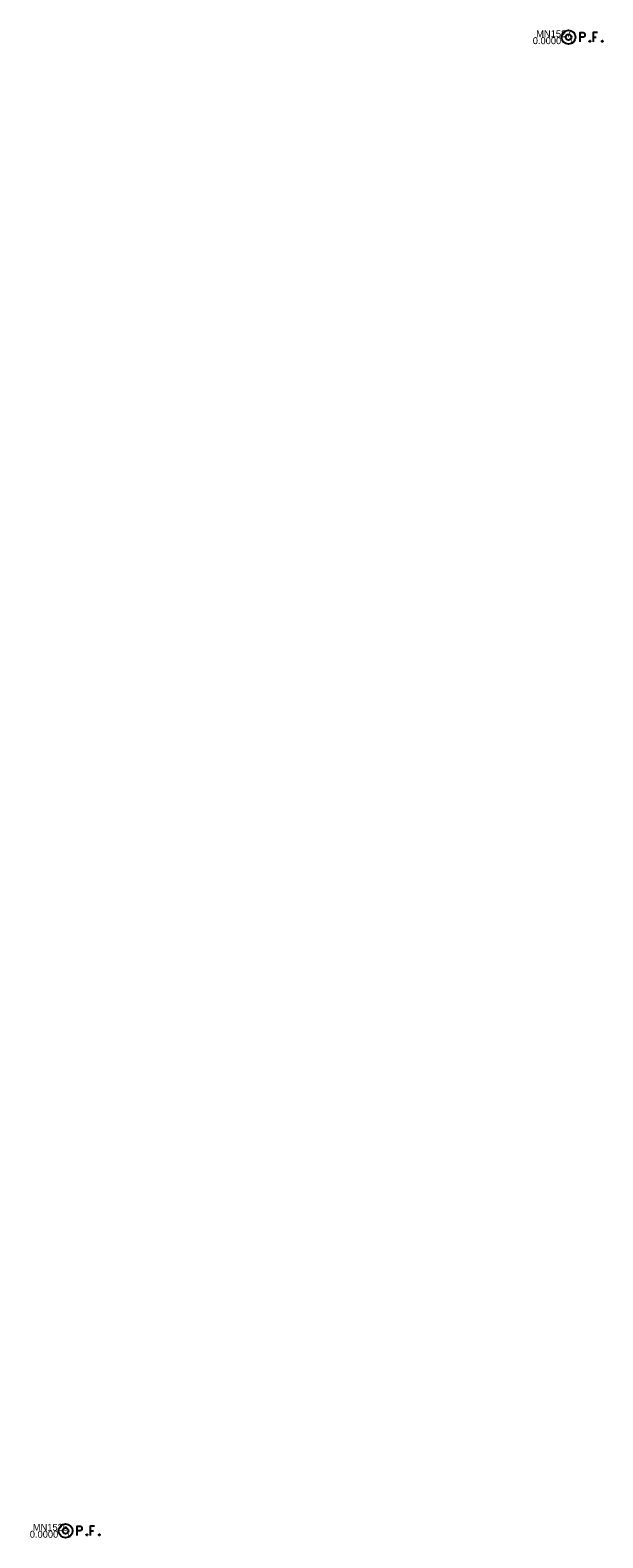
# Model space of a CAD drawing. Extents: x 182090 to 1832865, y 706265 to 714392.
# Drawn here: x 1823047.3 to 1823072, y 712547.6 to 712612.6 of the extents above; entities that cross this region are included whole.
import ezdxf

# ---------------------------------------------------------------- set-up
doc = ezdxf.new("R2010")
doc.units = 0
for name, color, linetype in [('SV_X_Mon_Cells_Found', 7, 'Continuous'), ('SV_X_Text_Comment', 7, 'Continuous'), ('SV_X_Text_Elevation', 7, 'Continuous'), ('SV_X_Text_Name', 7, 'Continuous')]:
    doc.layers.add(name, color=color, linetype=linetype)

msp = doc.modelspace()

# ---------------------------------------------------------------- linework, layer by layer
at = {"layer": 'SV_X_Mon_Cells_Found'}
for points in [[(1823070.993, 712612.107), (1823070.993, 712612.507), (1823071.126, 712612.507), (1823071.139, 712612.504), (1823071.159, 712612.498), (1823071.167, 712612.491), (1823071.175, 712612.485), (1823071.186, 712612.469), (1823071.194, 712612.453), (1823071.2, 712612.428), (1823071.2, 712612.39), (1823071.197, 712612.378), (1823071.192, 712612.359), (1823071.181, 712612.337), (1823071.17, 712612.327), (1823071.161, 712612.321), (1823071.148, 712612.315), (1823071.126, 712612.312), (1823070.993, 712612.312)], [(1823071.746, 712612.507), (1823071.555, 712612.507), (1823071.555, 712612.107)], [(1823071.404, 712612.161), (1823071.418, 712612.161), (1823071.426, 712612.154), (1823071.434, 712612.142), (1823071.434, 712612.126), (1823071.426, 712612.113), (1823071.418, 712612.107), (1823071.404, 712612.107), (1823071.396, 712612.113), (1823071.387, 712612.126), (1823071.387, 712612.142), (1823071.396, 712612.154), (1823071.404, 712612.161)], [(1823071.555, 712612.312), (1823071.691, 712612.312)], [(1823071.941, 712612.161), (1823071.955, 712612.161), (1823071.963, 712612.154), (1823071.972, 712612.142), (1823071.972, 712612.126), (1823071.963, 712612.113), (1823071.955, 712612.107), (1823071.941, 712612.107), (1823071.933, 712612.113), (1823071.925, 712612.126), (1823071.925, 712612.142), (1823071.933, 712612.154), (1823071.941, 712612.161)], [(1823049.3, 712547.671), (1823049.3, 712548.071), (1823049.433, 712548.071), (1823049.446, 712548.068), (1823049.466, 712548.062), (1823049.474, 712548.055), (1823049.482, 712548.049), (1823049.493, 712548.033), (1823049.501, 712548.017), (1823049.507, 712547.992), (1823049.507, 712547.954), (1823049.504, 712547.942), (1823049.499, 712547.923), (1823049.488, 712547.901), (1823049.477, 712547.891), (1823049.468, 712547.885), (1823049.455, 712547.879), (1823049.433, 712547.876), (1823049.3, 712547.876)], [(1823049.711, 712547.725), (1823049.725, 712547.725), (1823049.733, 712547.718), (1823049.741, 712547.706), (1823049.741, 712547.69), (1823049.733, 712547.677), (1823049.725, 712547.671), (1823049.711, 712547.671), (1823049.703, 712547.677), (1823049.694, 712547.69), (1823049.694, 712547.706), (1823049.703, 712547.718), (1823049.711, 712547.725)], [(1823050.053, 712548.071), (1823049.862, 712548.071), (1823049.862, 712547.671)], [(1823049.862, 712547.876), (1823049.998, 712547.876)], [(1823050.248, 712547.725), (1823050.262, 712547.725), (1823050.27, 712547.718), (1823050.279, 712547.706), (1823050.279, 712547.69), (1823050.27, 712547.677), (1823050.262, 712547.671), (1823050.248, 712547.671), (1823050.24, 712547.677), (1823050.232, 712547.69), (1823050.232, 712547.706), (1823050.24, 712547.718), (1823050.248, 712547.725)]]:
    msp.add_lwpolyline(points, dxfattribs=at)
for centre, radius in [((1823070.494, 712612.307), 0.3), ((1823070.494, 712612.307), 0.124), ((1823048.801, 712547.871), 0.3), ((1823048.801, 712547.871), 0.124)]:
    msp.add_circle(centre, radius, dxfattribs=at)

# ---------------------------------------------------------------- texts
at = {"layer": 'SV_X_Text_Comment'}
for p in [(1823070.494, 712612.007), (1823048.801, 712547.571)]:
    msp.add_text('1', height=0.3, dxfattribs=at).set_placement(p)
at = {"layer": 'SV_X_Text_Elevation'}
for p in [(1823068.949, 712612.007), (1823047.256, 712547.571)]:
    msp.add_text('0.0000', height=0.3, dxfattribs=at).set_placement(p)
at = {"layer": 'SV_X_Text_Name'}
for s, p in [('MN1527', (1823069.098, 712612.307)), ('MN1526', (1823047.386, 712547.871))]:
    msp.add_text(s, height=0.3, dxfattribs=at).set_placement(p)

doc.saveas('drawing.dxf')
